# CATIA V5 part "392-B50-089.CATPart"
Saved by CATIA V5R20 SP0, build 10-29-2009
Part number: 392-B50-089
Definition: NONE
Nomenclature: 392-B50-089
Source: Unknown
Description: 392-B50-089
Bounding box of the stored display mesh (mm): x 0 to 89, y -24.569 to 24.569, z -24.4 to 24.222
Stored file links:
  C:\Users\Utente\Desktop\IO LAVORO\3D X SITO CF\X SITO\3D files 392B\392-B50-089.CATPart
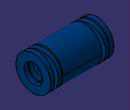
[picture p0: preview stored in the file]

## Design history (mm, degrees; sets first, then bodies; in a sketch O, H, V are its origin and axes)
Body1 "392-B50-089" (main body)
  Solid1: solid without history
